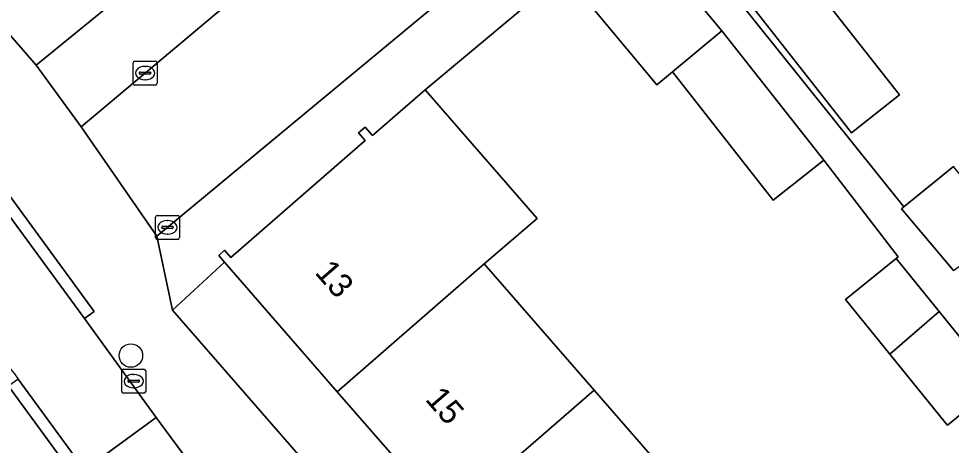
# Model space of a CAD drawing. Extents: x 162523 to 163266, y 381230 to 382050.
# Drawn here: x 162640.34 to 162679.21, y 381818.68 to 381836.46 of the extents above; entities that cross this region are included whole.
import ezdxf

# ---------------------------------------------------------------- set-up
doc = ezdxf.new("R2010")
doc.units = 0
for name, color, linetype in [('IMGEO_Boom', 7, 'Continuous'), ('IMGEO_Erf', 7, 'Continuous'), ('IMGEO_Kolk', 7, 'Continuous'), ('IMGEO_Muur', 7, 'Continuous'), ('IMGEO_Pand', 7, 'Continuous'), ('IMGEO_Pand_nummerreeks', 7, 'Continuous'), ('IMGEO_Rijbaan_lokaal_open', 7, 'Continuous'), ('IMGEO_Voetpad_open', 7, 'Continuous')]:
    doc.layers.add(name, color=color, linetype=linetype)

msp = doc.modelspace()

# ---------------------------------------------------------------- linework, layer by layer
at = {"layer": 'IMGEO_Boom'}
msp.add_circle((162645.021, 381822.421), 0.489, dxfattribs=at)
at = {"layer": 'IMGEO_Erf'}
for points in [[(162608.447, 381872.351), (162617.656, 381861.527), (162641.079, 381834.52), (162645.193, 381837.891), (162645.564, 381838.195), (162651.746, 381843.259), (162654.733, 381845.707), (162655.225, 381846.11), (162652.994, 381848.812), (162648.983, 381853.709), (162649.512, 381854.143), (162647.831, 381856.195), (162645.254, 381859.341), (162647.405, 381861.103), (162649.938, 381858.01), (162651.663, 381855.904), (162655.674, 381851.007), (162656.106, 381851.292), (162641.659, 381868.486)], [(162679.56, 381843.284), (162678.653, 381842.633), (162677.25, 381844.593), (162677.497, 381845.913), (162679.88, 381847.619), (162677.677, 381850.696), (162669.496, 381843.741), (162673.418, 381839.033), (162672.885, 381838.589), (162677.055, 381833.283), (162675.044, 381831.702), (162670.918, 381836.951), (162666.996, 381841.659), (162666.869, 381841.547), (162677.229, 381828.616), (162679.298, 381830.294)], [(162681.059, 381821.151), (162679.054, 381819.512), (162678.957, 381819.631), (162676.652, 381822.473), (162674.802, 381824.753), (162676.905, 381826.459), (162676.992, 381826.53), (162673.894, 381830.556), (162671.789, 381828.902), (162667.589, 381834.245), (162666.937, 381833.701), (162663.076, 381838.336), (162657.279, 381833.5), (162661.952, 381828.133), (162659.744, 381826.237), (162664.321, 381820.98), (162668.898, 381815.723), (162670.936, 381817.497), (162675.512, 381812.241), (162673.475, 381810.467), (162678.052, 381805.21), (162680.405, 381807.258)]]:
    msp.add_lwpolyline(points, dxfattribs=at)
msp.add_lwpolyline([(162646.757, 381824.316), (162687.062, 381778.024), (162692.677, 381771.414), (162694.979, 381773.409), (162690.237, 381778.855), (162685.66, 381784.112), (162681.084, 381789.369), (162676.507, 381794.626), (162671.93, 381799.882), (162667.354, 381805.138), (162662.776, 381810.395), (162658.2, 381815.652), (162653.622, 381820.909), (162648.917, 381826.314)], close=True, dxfattribs=at)
at = {"layer": 'IMGEO_Kolk'}
for p, q in [((162645.114, 381833.766), (162645.114, 381834.618)), ((162645.189, 381834.692), (162646.041, 381834.692)), ((162645.602, 381834.472), (162645.627, 381834.472)), ((162646.115, 381834.618), (162646.115, 381833.766)), ((162645.373, 381834.186), (162645.373, 381834.198)), ((162645.811, 381834.149), (162645.413, 381834.149)), ((162645.416, 381834.235), (162645.814, 381834.235)), ((162645.857, 381834.198), (162645.857, 381834.186)), ((162646.041, 381833.692), (162645.189, 381833.692)), ((162645.625, 381833.912), (162645.6, 381833.912)), ((162646.046, 381827.337), (162646.046, 381828.189)), ((162646.121, 381828.263), (162646.973, 381828.263)), ((162647.047, 381828.189), (162647.047, 381827.337)), ((162646.348, 381827.806), (162646.746, 381827.806)), ((162646.534, 381828.043), (162646.559, 381828.043)), ((162646.305, 381827.757), (162646.305, 381827.769)), ((162646.743, 381827.72), (162646.345, 381827.72)), ((162646.557, 381827.483), (162646.532, 381827.483)), ((162646.789, 381827.769), (162646.789, 381827.757)), ((162646.973, 381827.263), (162646.121, 381827.263)), ((162644.638, 381820.927), (162644.638, 381821.779)), ((162644.713, 381821.853), (162645.565, 381821.853)), ((162645.126, 381821.633), (162645.151, 381821.633)), ((162645.639, 381821.779), (162645.639, 381820.927)), ((162644.897, 381821.347), (162644.897, 381821.359)), ((162645.335, 381821.31), (162644.937, 381821.31)), ((162644.94, 381821.396), (162645.338, 381821.396)), ((162645.381, 381821.359), (162645.381, 381821.347)), ((162645.565, 381820.853), (162644.713, 381820.853)), ((162645.149, 381821.073), (162645.124, 381821.073))]:
    msp.add_line(p, q, dxfattribs=at)
for points in [[(162645.114, 381833.766), (162645.114, 381834.618)], [(162645.189, 381834.692), (162646.041, 381834.692)], [(162646.115, 381834.618), (162646.115, 381833.766)], [(162646.041, 381833.692), (162645.189, 381833.692)], [(162646.046, 381827.337), (162646.046, 381828.189)], [(162646.121, 381828.263), (162646.973, 381828.263)], [(162647.047, 381828.189), (162647.047, 381827.337)], [(162646.973, 381827.263), (162646.121, 381827.263)], [(162644.638, 381820.927), (162644.638, 381821.779)], [(162644.713, 381821.853), (162645.565, 381821.853)], [(162645.639, 381821.779), (162645.639, 381820.927)], [(162645.565, 381820.853), (162644.713, 381820.853)]]:
    msp.add_lwpolyline(points, dxfattribs=at)
for centre, radius, start, end in [((162645.191, 381834.616), 0.0765, 91.552, 178.448), ((162645.191, 381834.616), 0.0765, 91.552, 178.448), ((162646.039, 381834.616), 0.0765, 1.552, 88.448), ((162646.039, 381834.616), 0.0765, 1.552, 88.448), ((162645.413, 381834.195), 0.0403, 85.8775, 175.7526), ((162645.41, 381834.185), 0.0366, 178.938, 274.7102), ((162645.814, 381834.192), 0.043, 264.8664, 352.4533), ((162645.818, 381834.197), 0.0386, 1.7309, 96.639), ((162645.191, 381833.768), 0.0765, 181.552, 268.448), ((162645.191, 381833.768), 0.0765, 181.552, 268.448), ((162646.039, 381833.768), 0.0765, 271.552, 358.448), ((162646.039, 381833.768), 0.0765, 271.552, 358.448), ((162646.123, 381828.187), 0.0765, 91.552, 178.448), ((162646.123, 381828.187), 0.0765, 91.552, 178.448), ((162646.971, 381828.187), 0.0765, 1.552, 88.448), ((162646.971, 381828.187), 0.0765, 1.552, 88.448), ((162646.345, 381827.766), 0.0403, 85.8775, 175.7526), ((162646.75, 381827.768), 0.0386, 1.7309, 96.639), ((162646.342, 381827.756), 0.0366, 178.938, 274.7102), ((162646.746, 381827.763), 0.043, 264.8664, 352.4533), ((162646.123, 381827.339), 0.0765, 181.552, 268.448), ((162646.123, 381827.339), 0.0765, 181.552, 268.448), ((162646.971, 381827.339), 0.0765, 271.552, 358.448), ((162646.971, 381827.339), 0.0765, 271.552, 358.448), ((162644.715, 381821.777), 0.0765, 91.552, 178.448), ((162644.715, 381821.777), 0.0765, 91.552, 178.448), ((162645.563, 381821.777), 0.0765, 1.552, 88.448), ((162645.563, 381821.777), 0.0765, 1.552, 88.448), ((162644.937, 381821.356), 0.0403, 85.8775, 175.7526), ((162644.934, 381821.346), 0.0366, 178.938, 274.7102), ((162645.338, 381821.353), 0.043, 264.8664, 352.4533), ((162645.342, 381821.358), 0.0386, 1.7309, 96.639), ((162644.715, 381820.929), 0.0765, 181.552, 268.448), ((162644.715, 381820.929), 0.0765, 181.552, 268.448), ((162645.563, 381820.929), 0.0765, 271.552, 358.448), ((162645.563, 381820.929), 0.0765, 271.552, 358.448)]:
    msp.add_arc(centre, radius, start, end, dxfattribs=at)
for centre, major_axis, ratio, start_param, end_param in [((162645.601, 381834.192), (-0.387, 0.002), 0.722429, 4.712389, 7.853982), ((162645.626, 381834.192), (-0.39, 0.002), 0.717154, 1.570796, 4.712389), ((162646.533, 381827.763), (-0.387, 0.002), 0.722429, 4.712389, 7.853982), ((162646.558, 381827.763), (-0.39, 0.002), 0.717154, 1.570796, 4.712389), ((162645.125, 381821.353), (-0.387, 0.002), 0.722429, 4.712389, 7.853982), ((162645.15, 381821.353), (-0.39, 0.002), 0.717154, 1.570796, 4.712389)]:
    msp.add_ellipse(centre, major_axis=major_axis, ratio=ratio, start_param=start_param, end_param=end_param, dxfattribs=at)
at = {"layer": 'IMGEO_Muur'}
msp.add_lwpolyline([(162663.076, 381838.336), (162657.279, 381833.5)], dxfattribs=at)
at = {"layer": 'IMGEO_Pand'}
for points in [[(162665.786, 381840.593), (162663.076, 381838.336), (162666.937, 381833.701), (162667.589, 381834.245), (162669.647, 381835.959)], [(162672.885, 381838.589), (162670.918, 381836.951), (162675.044, 381831.702), (162677.055, 381833.283)], [(162669.647, 381835.959), (162667.589, 381834.245), (162671.789, 381828.902), (162673.894, 381830.556)], [(162653.622, 381820.909), (162659.744, 381826.237), (162661.952, 381828.133), (162657.279, 381833.5), (162655.084, 381831.589), (162654.782, 381831.936), (162654.506, 381831.695), (162654.779, 381831.382), (162649.184, 381826.51), (162648.928, 381826.805), (162648.679, 381826.587), (162648.917, 381826.314)], [(162677.229, 381828.616), (162677.13, 381828.535), (162679.299, 381825.961), (162679.595, 381826.173), (162680.17, 381826.585), (162681.414, 381827.475), (162681.522, 381827.552), (162679.298, 381830.294)], [(162658.2, 381815.652), (162664.321, 381820.98), (162659.744, 381826.237), (162653.622, 381820.909)], [(162676.905, 381826.459), (162674.802, 381824.753), (162676.652, 381822.473), (162678.696, 381824.251)], [(162678.696, 381824.251), (162676.652, 381822.473), (162678.957, 381819.631), (162679.054, 381819.512), (162681.059, 381821.151), (162681.155, 381821.22)], [(162662.776, 381810.395), (162668.898, 381815.723), (162664.321, 381820.98), (162658.2, 381815.652)]]:
    msp.add_lwpolyline(points, close=True, dxfattribs=at)
at = {"layer": 'IMGEO_Rijbaan_lokaal_open'}
for points in [[(162695.216, 381867.785), (162698.457, 381870.411), (162694.996, 381874.59), (162688.855, 381869.619), (162681.316, 381863.363), (162672.848, 381856.46), (162665.027, 381850.088), (162661.191, 381846.959), (162656.652, 381843.257), (162653.131, 381840.384), (162648.579, 381836.677), (162642.953, 381831.956), (162646.101, 381827.394), (162660.46, 381839.32), (162661.37, 381840.059), (162668.127, 381845.543), (162676.395, 381852.319)], [(162614.774, 381852.067), (162616.934, 381849.61), (162617.086, 381849.434), (162631.239, 381833.128), (162632.331, 381831.841), (162633.584, 381830.334), (162640.035, 381821.827), (162640.168, 381821.652), (162640.326, 381821.437), (162643.092, 381817.657), (162646.081, 381819.844), (162643.084, 381823.959), (162638.563, 381830.136), (162637.168, 381832.042), (162637.013, 381832.223), (162626.638, 381844.343), (162617.781, 381854.439), (162610.879, 381862.225)]]:
    msp.add_lwpolyline(points, dxfattribs=at)
msp.add_lwpolyline([(162647.554, 381817.822), (162646.081, 381819.844), (162643.092, 381817.657), (162643.404, 381817.231), (162643.843, 381816.631), (162644.181, 381816.17), (162645.167, 381814.823), (162648.176, 381817.107)], close=True, dxfattribs=at)
at = {"layer": 'IMGEO_Voetpad_open'}
for points in [[(162646.757, 381824.316), (162646.101, 381827.394), (162642.953, 381831.956), (162641.079, 381834.52), (162617.656, 381861.527), (162608.447, 381872.351), (162604.976, 381869.467)], [(162682.745, 381857.472), (162676.395, 381852.319), (162668.127, 381845.543), (162668.442, 381845.156), (162661.685, 381839.672), (162661.37, 381840.059), (162660.46, 381839.32), (162646.101, 381827.394), (162646.757, 381824.316), (162648.917, 381826.314), (162648.679, 381826.587), (162648.928, 381826.805), (162649.184, 381826.51), (162654.779, 381831.382), (162654.506, 381831.695), (162654.782, 381831.936), (162655.084, 381831.589), (162657.279, 381833.5), (162663.076, 381838.336)], [(162679.299, 381825.961), (162677.13, 381828.535), (162677.229, 381828.616), (162666.869, 381841.547), (162665.786, 381840.593), (162669.647, 381835.959), (162673.894, 381830.556), (162676.992, 381826.53), (162676.905, 381826.459), (162678.696, 381824.251), (162681.155, 381821.22)], [(162637.013, 381832.223), (162637.168, 381832.042), (162638.563, 381830.136), (162638.966, 381830.431), (162643.487, 381824.254), (162643.084, 381823.959), (162646.081, 381819.844), (162647.554, 381817.822)], [(162695.37, 381768.61), (162698.385, 381769.691), (162696.883, 381771.248), (162695.203, 381773.152), (162694.979, 381773.409), (162692.677, 381771.414), (162687.062, 381778.024), (162646.757, 381824.316)], [(162645.988, 381813.796), (162645.795, 381814.018), (162645.551, 381814.298), (162645.167, 381814.823), (162644.181, 381816.17), (162643.843, 381816.631), (162643.44, 381816.336), (162639.923, 381821.142)]]:
    msp.add_lwpolyline(points, dxfattribs=at)
for points in [[(162653.131, 381840.384), (162656.652, 381843.257), (162656.336, 381843.643), (162654.733, 381845.707), (162651.746, 381843.259), (162645.564, 381838.195), (162645.193, 381837.891), (162641.079, 381834.52), (162642.953, 381831.956), (162648.579, 381836.677)], [(162643.084, 381823.959), (162643.487, 381824.254), (162638.966, 381830.431), (162638.563, 381830.136)], [(162640.326, 381821.437), (162639.923, 381821.142), (162643.44, 381816.336), (162643.843, 381816.631), (162643.404, 381817.231), (162643.092, 381817.657)]]:
    msp.add_lwpolyline(points, close=True, dxfattribs=at)

# ---------------------------------------------------------------- texts
at = {"layer": 'IMGEO_Pand_nummerreeks'}
for s, p in [('13', (162652.652, 381825.861)), ('15', (162657.251, 381820.579))]:
    msp.add_text(s, height=1, rotation=311.0448, dxfattribs=at).set_placement(p)

doc.saveas('drawing.dxf')
